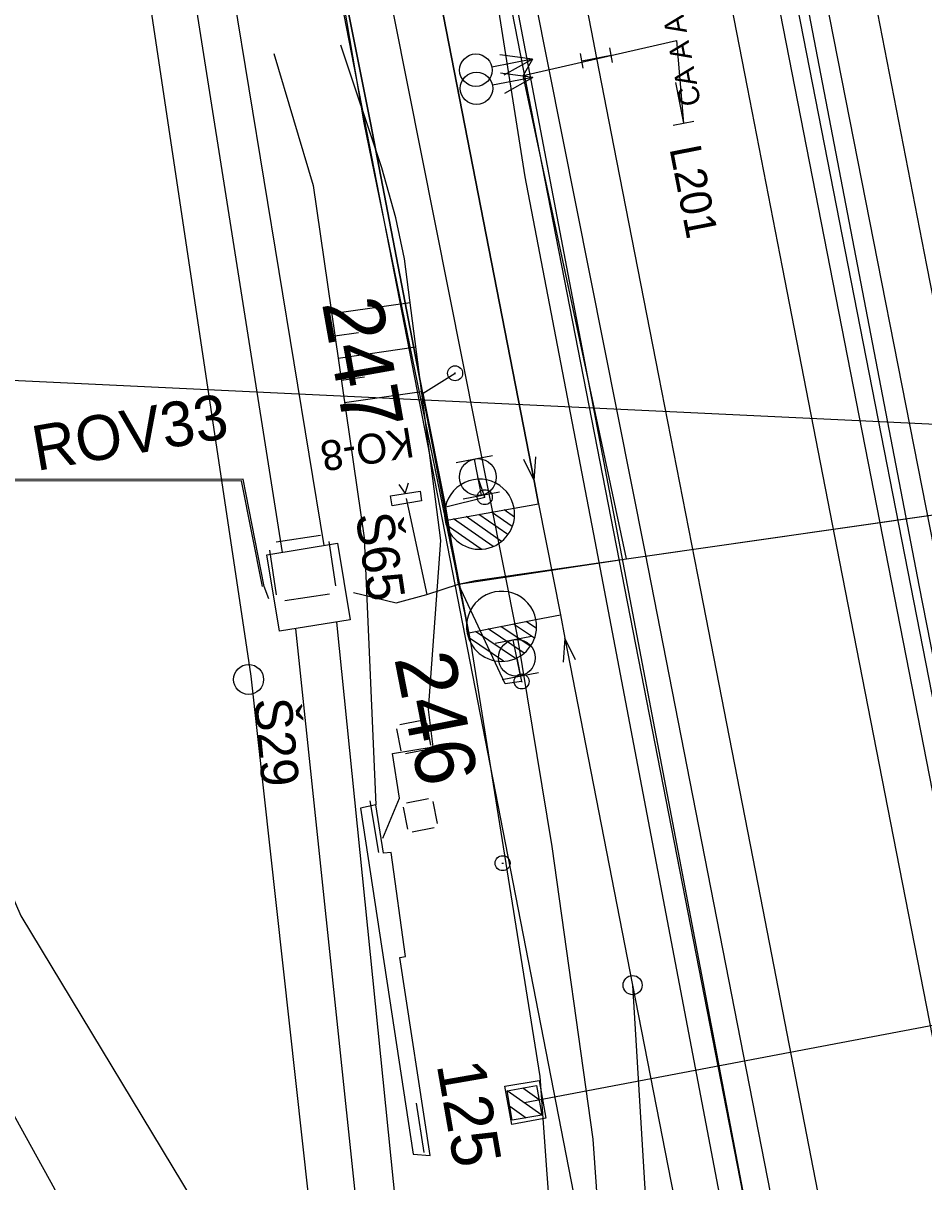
# Model space of a CAD drawing. Extents: x -545846 to -545044, y -1122650 to -1119108.
# Drawn here: x -545637.44 to -545607.35, y -1119747.46 to -1119708.74 of the extents above; entities that cross this region are included whole.
import ezdxf

# ---------------------------------------------------------------- set-up
doc = ezdxf.new("R2010")
doc.units = 0
for name, color, linetype in [('osvětlené plochy-hodnota-obrys', 7, 'Continuous'), ('Vrstva 1 - Koleje', 7, 'Continuous'), ('Vrstva 11 - Trakce', 7, 'Continuous'), ('Vrstva 12', 7, 'Continuous'), ('Vrstva 12 - Trakce zaklady', 7, 'Continuous'), ('Vrstva 17', 7, 'Continuous'), ('Vrstva 2 - Vyhybky', 7, 'Continuous'), ('Vrstva 25', 7, 'Continuous'), ('Vrstva 26', 7, 'Continuous'), ('Vrstva 27', 7, 'Continuous'), ('Vrstva 28 - zabzar', 7, 'Continuous'), ('Vrstva 3 - Lisy - Pocitaci body', 7, 'Continuous'), ('Vrstva 31', 7, 'Continuous'), ('Vrstva 34', 7, 'Continuous'), ('Vrstva 35', 7, 'Continuous'), ('Vrstva 36', 7, 'Continuous'), ('Vrstva 4 - Teren - stezky - prechody - plochy', 7, 'Continuous'), ('Vrstva 41', 7, 'Continuous'), ('Vrstva 43', 7, 'Continuous'), ('Vrstva 44', 7, 'Continuous'), ('Vrstva 48', 7, 'Continuous'), ('Vrstva 49', 7, 'Continuous'), ('Vrstva 50', 7, 'Continuous'), ('Vrstva 6 - Navesti', 7, 'Continuous'), ('Vrstva 62', 7, 'Continuous'), ('Vrstva 63', 7, 'Continuous')]:
    doc.layers.add(name, color=color, linetype=linetype)

msp = doc.modelspace()

# ---------------------------------------------------------------- linework, layer by layer
at = {"layer": 'osvětlené plochy-hodnota-obrys'}
for points in [[(-545716.386, -1119223.717), (-545705.994, -1119221.66), (-545669.439, -1119408.759), (-545659.4, -1119462.635), (-545647.69, -1119521.347), (-545640.519, -1119558.729), (-545633.585, -1119589.698), (-545629.517, -1119613.814), (-545623.042, -1119645.057), (-545619.034, -1119667.556), (-545607.519, -1119727.517)], [(-545610.895, -1119760.665), (-545622.836, -1119699.488), (-545637.26, -1119626.872), (-545653.542, -1119543.449), (-545716.386, -1119223.717)], [(-545618.794, -1119749.17), (-545664.282, -1119515.639)], [(-545607.519, -1119727.517), (-545482.536, -1120367.871), (-545465.73, -1120446.743)]]:
    msp.add_lwpolyline(points, dxfattribs=at)
at = {"layer": 'Vrstva 1 - Koleje'}
for points in [[(-545620.224, -1119724.797), (-545620.373, -1119724.031), (-545624.202, -1119704.383), (-545626.602, -1119682.532), (-545627.256, -1119676.573), (-545628.042, -1119669.394), (-545630.443, -1119647.544), (-545633.496, -1119631.903), (-545634.274, -1119627.915), (-545634.427, -1119627.13)], [(-545615.292, -1119700.416), (-545613.256, -1119710.876), (-545612.083, -1119716.896), (-545610.167, -1119726.739), (-545608.467, -1119735.46), (-545606.677, -1119744.638), (-545604.634, -1119755.121), (-545602.627, -1119765.413), (-545600.596, -1119775.823), (-545598.487, -1119786.628), (-545596.43, -1119797.186), (-545594.376, -1119807.724), (-545592.296, -1119818.383), (-545590.271, -1119828.778), (-545588.207, -1119839.366), (-545586.589, -1119847.665), (-545583.547, -1119863.26), (-545581.482, -1119873.852), (-545579.437, -1119884.331), (-545577.669, -1119893.4)], [(-545620.04, -1119700.93), (-545618.466, -1119708.981), (-545618.287, -1119709.904), (-545617.707, -1119712.885), (-545616.218, -1119720.514), (-545614.817, -1119727.693), (-545612.814, -1119737.973), (-545610.755, -1119748.533), (-545609.137, -1119756.825), (-545607.54, -1119765.023), (-545606.208, -1119771.849), (-545604.163, -1119782.329), (-545602.108, -1119792.879), (-545600.005, -1119803.67), (-545598.048, -1119813.712), (-545596.051, -1119823.937), (-545594.041, -1119834.228), (-545591.245, -1119848.57), (-545589.268, -1119858.708), (-545587.271, -1119868.949), (-545585.312, -1119878.984), (-545583.448, -1119888.544), (-545581.461, -1119898.732)], [(-545624.202, -1119704.383), (-545620.373, -1119724.031), (-545620.224, -1119724.797)], [(-545609.289, -1119706.39), (-545607.258, -1119716.828), (-545605.385, -1119726.4), (-545604.749, -1119729.676), (-545602.629, -1119740.555), (-545600.686, -1119750.508), (-545598.795, -1119760.226), (-545596.798, -1119770.466), (-545594.897, -1119780.215), (-545592.936, -1119790.271), (-545591.004, -1119800.184), (-545589.134, -1119809.787), (-545587.162, -1119819.904), (-545585.454, -1119828.656), (-545583.635, -1119837.965), (-545581.894, -1119846.888), (-545579.772, -1119857.774), (-545577.858, -1119867.605), (-545575.847, -1119877.904), (-545574.063, -1119887.086), (-545572.15, -1119896.857)], [(-545620.224, -1119724.797), (-545619.495, -1119728.51)], [(-545619.495, -1119728.51), (-545619.342, -1119729.295), (-545617.081, -1119740.889), (-545616.115, -1119756.897), (-545615.896, -1119760.311), (-545615.76, -1119762.434)], [(-545619.495, -1119728.51), (-545619.342, -1119729.295), (-545617.081, -1119740.889), (-545614.014, -1119756.616), (-545613.347, -1119760.026), (-545611.356, -1119770.277), (-545609.291, -1119780.868), (-545607.284, -1119791.169), (-545605.791, -1119798.836), (-545605.539, -1119800.128), (-545603.55, -1119810.316), (-545601.73, -1119819.637), (-545599.797, -1119829.553), (-545597.8, -1119839.791), (-545595.924, -1119849.399), (-545593.688, -1119860.879), (-545591.957, -1119869.777), (-545589.995, -1119879.817), (-545588.126, -1119889.394), (-545586.206, -1119899.252)]]:
    msp.add_lwpolyline(points, dxfattribs=at)
at = {"layer": 'Vrstva 11 - Trakce'}
for p, q in [((-545621.27, -1119744.417), (-545620.117, -1119745.229)), ((-545620.748, -1119744.327), (-545620.208, -1119744.707)), ((-545621.183, -1119744.937), (-545620.636, -1119745.322))]:
    msp.add_line(p, q, dxfattribs=at)
msp.add_lwpolyline([(-545556.873, -1119732.708), (-545581.366, -1119737.374), (-545620.695, -1119744.825)], dxfattribs=at)
msp.add_lwpolyline([(-545620.288, -1119744.247), (-545620.117, -1119745.232), (-545621.102, -1119745.403), (-545621.273, -1119744.418)], close=True, dxfattribs=at)
at = {"layer": 'Vrstva 12'}
msp.add_lwpolyline([(-545625.148, -1119736.458), (-545625.404, -1119736.479), (-545625.662, -1119734.867), (-545626.175, -1119734.971), (-545624.412, -1119746.538), (-545623.847, -1119746.584), (-545624.862, -1119739.966), (-545624.668, -1119739.936)], close=True, dxfattribs=at)
at = {"layer": 'Vrstva 12 - Trakce zaklady'}
msp.add_lwpolyline([(-545620.2, -1119744.079), (-545619.982, -1119745.334), (-545621.111, -1119745.55), (-545621.345, -1119744.265), (-545620.2, -1119744.079)], dxfattribs=at)
at = {"layer": 'Vrstva 17'}
for p, q in [((-545625.864, -1119734.724), (-545625.569, -1119736.452)), ((-545624.314, -1119744.838), (-545624.052, -1119746.488))]:
    msp.add_line(p, q, dxfattribs=at)
at = {"layer": 'Vrstva 2 - Vyhybky'}
for p, q in [((-545623.347, -1119725.355), (-545621.042, -1119724.945)), ((-545621.029, -1119725.244), (-545621.373, -1119725.004)), ((-545621.042, -1119724.945), (-545620.224, -1119724.797)), ((-545623.347, -1119725.356), (-545623.347, -1119725.355)), ((-545621.744, -1119726.228), (-545623.066, -1119725.305)), ((-545621.457, -1119726.057), (-545622.643, -1119725.23)), ((-545621.247, -1119725.833), (-545622.219, -1119725.154)), ((-545621.101, -1119725.564), (-545621.796, -1119725.08)), ((-545622.145, -1119726.318), (-545623.307, -1119725.508)), ((-545620.31, -1119728.672), (-545619.495, -1119728.51)), ((-545622.608, -1119729.123), (-545620.31, -1119728.672)), ((-545620.5, -1119729.564), (-545621.484, -1119728.902)), ((-545620.359, -1119729.293), (-545621.062, -1119728.82)), ((-545620.292, -1119728.971), (-545620.64, -1119728.737)), ((-545622.608, -1119729.124), (-545622.608, -1119729.123)), ((-545621.389, -1119730.065), (-545622.565, -1119729.275)), ((-545620.989, -1119729.968), (-545622.328, -1119729.068)), ((-545620.706, -1119729.791), (-545621.906, -1119728.985))]:
    msp.add_line(p, q, dxfattribs=at)
for points in [[(-545628.408, -1119682.795), (-545624.202, -1119704.383), (-545620.373, -1119724.031), (-545620.224, -1119724.797)], [(-545620.724, -1119723.312), (-545620.373, -1119724.031), (-545620.318, -1119723.233)], [(-545619.495, -1119728.51), (-545619.342, -1119729.295), (-545617.081, -1119740.889), (-545614.014, -1119756.616)], [(-545618.991, -1119730.014), (-545619.342, -1119729.295), (-545619.397, -1119730.093)], [(-545617.081, -1119740.889), (-545616.115, -1119756.897)]]:
    msp.add_lwpolyline(points, dxfattribs=at)
msp.add_circle((-545617.081, -1119740.889), 0.32, dxfattribs=at)
for centre, radius, start, end in [((-545622.193, -1119725.149), 1.17, 10.0337, 190.5033), ((-545622.194, -1119725.15), 1.171, 190.1233, 10.0841), ((-545621.458, -1119728.896), 1.17, 11.0374, 191.507), ((-545621.459, -1119728.898), 1.171, 191.127, 11.0878)]:
    msp.add_arc(centre, radius, start, end, dxfattribs=at)
at = {"layer": 'Vrstva 26'}
msp.add_lwpolyline([(-545629.45, -1119727.57), (-545630.15, -1119724.03), (-545639.1, -1119724.04), (-545639.35, -1119723.56), (-545638.56, -1119723.44), (-545638.81, -1119723.24), (-545638.97, -1119722.74), (-545638.995, -1119722.515), (-545638.995, -1119722.515)], dxfattribs=at)
at = {"layer": 'Vrstva 27'}
for p, q in [((-545625.17, -1119724.539), (-545625.167, -1119724.535)), ((-545622.015, -1119724.605), (-545622.025, -1119724.555)), ((-545620.794, -1119730.715), (-545620.786, -1119730.765))]:
    msp.add_line(p, q, dxfattribs=at)
msp.add_lwpolyline([(-545624.894, -1119724.153), (-545624.677, -1119724.455), (-545624.565, -1119724.1)], dxfattribs=at)
msp.add_lwpolyline([(-545625.17, -1119724.535), (-545624.183, -1119724.376), (-545624.13, -1119724.705), (-545625.117, -1119724.864)], close=True, dxfattribs=at)
for centre in [(-545622.02, -1119724.58), (-545620.79, -1119730.74)]:
    msp.add_circle(centre, 0.25, dxfattribs=at)
at = {"layer": 'Vrstva 28 - zabzar'}
msp.add_line((-545623.01, -1119720.465), (-545623.01, -1119720.415), dxfattribs=at)
for points in [[(-545626.41, -1119727.77), (-545624.98, -1119728.11), (-545623.96, -1119727.83), (-545622.9, -1119727.49), (-545622.33, -1119727.37), (-545617.28, -1119726.64), (-545619.25, -1119717.45), (-545620.74, -1119710.48), (-545615.61, -1119709.32), (-545615.38, -1119712.08)], [(-545620.43, -1119709.94), (-545620.74, -1119710.48), (-545620.41, -1119710.55)], [(-545620.95, -1119729.95), (-545620.79, -1119730.74), (-545621.34, -1119730.82), (-545622.9, -1119727.49), (-545623.32, -1119724.9), (-545624.08, -1119721.1), (-545623.01, -1119720.44)], [(-545623.32, -1119724.9), (-545622.02, -1119724.58), (-545622.25, -1119723.91)], [(-545624.65, -1119724.62), (-545624.51, -1119725.24), (-545623.96, -1119727.83)], [(-545617.28, -1119726.64), (-545602.93, -1119724.58)]]:
    msp.add_lwpolyline(points, dxfattribs=at)
msp.add_circle((-545623.01, -1119720.44), 0.25, dxfattribs=at)
at = {"layer": 'Vrstva 3 - Lisy - Pocitaci body'}
for p, q in [((-545620.43, -1119709.94), (-545621.784, -1119710.205)), ((-545620.43, -1119709.94), (-545621.512, -1119709.8)), ((-545620.43, -1119709.94), (-545621.379, -1119710.477)), ((-545618.73, -1119710.245), (-545618.826, -1119709.754)), ((-545618.778, -1119709.999), (-545617.796, -1119709.809)), ((-545617.748, -1119710.054), (-545617.844, -1119709.563)), ((-545620.41, -1119710.55), (-545621.765, -1119710.814)), ((-545620.41, -1119710.55), (-545621.492, -1119710.409)), ((-545620.41, -1119710.55), (-545621.36, -1119711.086)), ((-545622.973, -1119723.423), (-545621.763, -1119723.187)), ((-545622.132, -1119724.515), (-545622.368, -1119723.305)), ((-545622.737, -1119724.633), (-545621.527, -1119724.397)), ((-545621.673, -1119729.463), (-545620.463, -1119729.227)), ((-545620.832, -1119730.555), (-545621.068, -1119729.345)), ((-545621.437, -1119730.673), (-545620.227, -1119730.437))]:
    msp.add_line(p, q, dxfattribs=at)
for centre, radius in [((-545622.317, -1119710.307), 0.542), ((-545622.297, -1119710.915), 0.542), ((-545622.251, -1119723.908), 0.616), ((-545620.951, -1119729.948), 0.616)]:
    msp.add_circle(centre, radius, dxfattribs=at)
at = {"layer": 'Vrstva 31'}
for points in [[(-545629.45, -1119727.57), (-545630.15, -1119724.03), (-545639.1, -1119724.04), (-545638.56, -1119723.44)], [(-545629.238, -1119727.978), (-545629.39, -1119727.57), (-545630.09, -1119723.98), (-545638.456, -1119723.984), (-545638.56, -1119723.44)]]:
    msp.add_lwpolyline(points, dxfattribs=at)
at = {"layer": 'Vrstva 34'}
for p, q in [((-545628.993, -1119726.071), (-545627.51, -1119725.849)), ((-545627.225, -1119726.059), (-545627.003, -1119727.542)), ((-545628.981, -1119727.839), (-545629.203, -1119726.356)), ((-545627.213, -1119727.827), (-545628.696, -1119728.049))]:
    msp.add_line(p, q, dxfattribs=at)
at = {"layer": 'Vrstva 35'}
for p, q in [((-545628.775, -1119726.428), (-545634.574, -1119689.677)), ((-545627.388, -1119726.198), (-545633.404, -1119689.501)), ((-545620.74, -1119710.48), (-545615.61, -1119709.32)), ((-545617.28, -1119726.64), (-545602.93, -1119724.58)), ((-545622.9, -1119727.49), (-545617.28, -1119726.64)), ((-545622.536, -1119772.489), (-545626.966, -1119728.759)), ((-545623.729, -1119772.61), (-545628.334, -1119728.982))]:
    msp.add_line(p, q, dxfattribs=at)
at = {"layer": 'Vrstva 36'}
for points in [[(-545629.3, -1119726.511), (-545626.94, -1119726.115), (-545626.518, -1119728.679), (-545628.873, -1119729.062), (-545629.3, -1119726.511)], [(-545629.3, -1119726.511), (-545626.94, -1119726.115)], [(-545626.94, -1119726.115), (-545626.94, -1119726.115), (-545626.518, -1119728.679), (-545626.518, -1119728.679)], [(-545628.873, -1119729.062), (-545629.3, -1119726.511), (-545629.3, -1119726.511)], [(-545626.518, -1119728.679), (-545628.873, -1119729.062), (-545628.873, -1119729.062)]]:
    msp.add_lwpolyline(points, dxfattribs=at)
at = {"layer": 'Vrstva 4 - Teren - stezky - prechody - plochy'}
for points in [[(-545668.116, -1119499.514), (-545665.721, -1119507.929), (-545662.615, -1119519.622), (-545659.148, -1119534.332), (-545655.765, -1119550.675), (-545641.939, -1119621.169), (-545637.993, -1119641.248), (-545631.568, -1119675.037), (-545626.43, -1119701.616), (-545620.933, -1119729.23), (-545619.776, -1119736.256), (-545618.414, -1119746.042), (-545618.118, -1119750.155), (-545617.307, -1119763.323), (-545616.619, -1119772.592), (-545616.223, -1119779.957), (-545616.135, -1119786.617)], [(-545628.853, -1119622.763), (-545624.686, -1119644.063), (-545616.354, -1119686.873), (-545605.869, -1119740.58), (-545597.619, -1119782.547), (-545588.666, -1119828.365), (-545577.778, -1119884.555), (-545567.555, -1119936.921), (-545555.278, -1120000.024), (-545543.118, -1120062.357), (-545532.633, -1120116.151), (-545522.436, -1120168.075), (-545510.345, -1120230.332), (-545500.633, -1120280.001), (-545495.304, -1120307.199), (-545490.342, -1120331.504), (-545485.9, -1120353.688), (-545480.839, -1120378)], [(-545627.289, -1119622.488), (-545623.041, -1119643.798), (-545614.848, -1119686.378), (-545604.257, -1119740.381), (-545596.077, -1119782.585), (-545587.168, -1119828.353), (-545576.202, -1119884.317), (-545565.971, -1119936.976), (-545553.74, -1119999.834), (-545541.535, -1120062.236), (-545531.079, -1120116.013), (-545520.819, -1120168.515), (-545508.831, -1120230.344), (-545499.12, -1120279.845), (-545497.248, -1120289.164), (-545495.162, -1120299.078), (-545493.408, -1120306.853), (-545489.261, -1120323.659), (-545486.768, -1120332.638), (-545482.019, -1120349.033), (-545479.258, -1120359.037), (-545477.044, -1120368.814), (-545475.362, -1120376.928)], [(-545637.393, -1119653.539), (-545633.274, -1119675.3), (-545627.579, -1119703.177), (-545627.31, -1119704.719), (-545626.06, -1119712.07), (-545622.496, -1119729.428)], [(-545488.754, -1120379.549), (-545491.925, -1120363.788), (-545496.278, -1120342.782), (-545500.506, -1120321.731), (-545508.599, -1120280.828), (-545518.82, -1120228.621), (-545531.029, -1120165.923), (-545540.626, -1120116.248), (-545552.245, -1120057.042), (-545557.488, -1120030.03), (-545563.439, -1119999.512), (-545572.128, -1119954.79), (-545581.61, -1119906.246), (-545591.458, -1119855.639), (-545600.962, -1119806.943), (-545610.434, -1119758.233), (-545616.648, -1119726.461), (-545621.696, -1119701.088), (-545622.533, -1119696.196), (-545623.462, -1119696.331)], [(-545490.916, -1120379.972), (-545493.99, -1120364.147), (-545502.163, -1120322.09), (-545510.164, -1120281.035), (-545520.235, -1120229.023), (-545532.517, -1120166.017), (-545542.296, -1120116.028), (-545553.809, -1120057.082), (-545558.932, -1120030.597), (-545564.969, -1119999.794), (-545573.753, -1119955.036), (-545583.127, -1119906.578), (-545593.017, -1119855.856), (-545602.553, -1119806.891), (-545612.123, -1119758.671), (-545618.333, -1119726.047), (-545620.676, -1119713.873), (-545622.612, -1119701.558), (-545623.462, -1119696.331)], [(-545622.496, -1119729.428), (-545625.835, -1119712.063), (-545627.31, -1119704.719)], [(-545627.31, -1119704.719), (-545625.835, -1119712.063), (-545622.496, -1119729.428), (-545620.183, -1119743.94), (-545619.945, -1119747.203), (-545618.749, -1119763.231), (-545617.479, -1119774.393), (-545617.097, -1119780.69), (-545617.068, -1119786.701), (-545616.135, -1119786.617)]]:
    msp.add_lwpolyline(points, dxfattribs=at)
at = {"layer": 'Vrstva 41'}
for p, q in [((-545624.81, -1119733.059), (-545624.953, -1119732.322)), ((-545624.855, -1119732.176), (-545624.118, -1119732.033)), ((-545623.972, -1119732.131), (-545623.829, -1119732.868)), ((-545623.927, -1119733.014), (-545624.664, -1119733.157)), ((-545624.636, -1119734.795), (-545623.9, -1119734.651)), ((-545624.591, -1119735.678), (-545624.735, -1119734.942)), ((-545623.753, -1119734.75), (-545623.609, -1119735.486)), ((-545623.708, -1119735.633), (-545624.444, -1119735.777))]:
    msp.add_line(p, q, dxfattribs=at)
at = {"layer": 'Vrstva 43'}
msp.add_circle((-545629.91, -1119730.672), 0.5, dxfattribs=at)
at = {"layer": 'Vrstva 44'}
for points in [[(-545654.9, -1119582.222), (-545645.965, -1119631.818), (-545637.145, -1119681.816), (-545629.836, -1119730.566), (-545626.416, -1119761.521), (-545622.849, -1119813.009), (-545619.592, -1119863.304), (-545618.858, -1119914.175), (-545618.881, -1119950.565), (-545618.715, -1119963.415), (-545629.02, -1119997.179)], [(-545622.746, -1119648.835), (-545613.361, -1119699.038), (-545602.122, -1119756.581), (-545611.004, -1119758.624), (-545611.36, -1119758.757)], [(-545632.322, -1119650.948), (-545622.321, -1119700.988), (-545611.338, -1119758.596), (-545611.36, -1119758.757), (-545611.449, -1119758.784)]]:
    msp.add_lwpolyline(points, dxfattribs=at)
at = {"layer": 'Vrstva 48'}
for p, q in [((-545627.132, -1119718.446), (-545624.516, -1119718.068)), ((-545627.025, -1119719.188), (-545626.243, -1119719.075)), ((-545626.918, -1119719.93), (-545624.323, -1119719.556)), ((-545626.811, -1119720.672), (-545626.036, -1119720.561)), ((-545626.704, -1119721.415), (-545624.131, -1119721.044))]:
    msp.add_line(p, q, dxfattribs=at)
at = {"layer": 'Vrstva 49'}
msp.add_line((-545625.464, -1119713.575), (-545626.833, -1119709.475), dxfattribs=at)
for points in [[(-545629.072, -1119709.755), (-545627.75, -1119714.159), (-545626.051, -1119725.941), (-545625.662, -1119734.867)], [(-545625.431, -1119735.975), (-545624.865, -1119734.64), (-545625.106, -1119733.146), (-545623.741, -1119732.926), (-545623.897, -1119731.682), (-545623.486, -1119726.025), (-545624.705, -1119716.608), (-545624.986, -1119715.238), (-545625.464, -1119713.575)]]:
    msp.add_lwpolyline(points, dxfattribs=at)
at = {"layer": 'Vrstva 50'}
msp.add_line((-545621.45, -1119736.813), (-545621.4, -1119736.813), dxfattribs=at)
msp.add_circle((-545621.425, -1119736.813), 0.25, dxfattribs=at)
at = {"layer": 'Vrstva 6 - Navesti'}
for p, q in [((-545615.646, -1119710.72), (-545615.38, -1119712.08)), ((-545615.723, -1119712.147), (-545615.037, -1119712.013))]:
    msp.add_line(p, q, dxfattribs=at)
at = {"layer": 'Vrstva 62'}
for points in [[(-545640.514, -1119731.132), (-545640.565, -1119731.562), (-545637.52, -1119738.574), (-545631.121, -1119749.176), (-545627.046, -1119780.523), (-545625.616, -1119808.19), (-545622.475, -1119817.927), (-545620.564, -1119842.07), (-545627.793, -1119850.696), (-545627.914, -1119866.869), (-545625.298, -1119872.204), (-545622.371, -1119881.231), (-545621.372, -1119899.088), (-545619.713, -1119906.036), (-545619.415, -1119919.615), (-545622.171, -1119926.525), (-545621.036, -1119950.949)], [(-545638.201, -1119873.676), (-545634.87, -1119872.217), (-545634.795, -1119868.379), (-545631.845, -1119861.885), (-545633.332, -1119850.19), (-545628.466, -1119836.59), (-545630.287, -1119812.477), (-545629.754, -1119789.831), (-545632.421, -1119759.531), (-545636.379, -1119747.707), (-545644.025, -1119733.886)]]:
    msp.add_lwpolyline(points, dxfattribs=at)
at = {"layer": 'Vrstva 63'}
msp.add_line((-545558.013, -1119724.486), (-545666.337, -1119719.323), dxfattribs=at)

# ---------------------------------------------------------------- texts
at = {"layer": 'Vrstva 11 - Trakce'}
msp.add_text('125', height=1.6, rotation=279.8542, dxfattribs=at).set_placement((-545623.63, -1119743.545))
at = {"layer": 'Vrstva 2 - Vyhybky'}
for s, rotation, p in [('247', 280.1037, (-545627.464, -1119718.088)), ('246', 281.0392, (-545625.047, -1119729.961))]:
    msp.add_text(s, height=2, rotation=rotation, dxfattribs=at).set_placement(p)
at = {"layer": 'Vrstva 25'}
msp.add_text('ROV33', height=1.5, rotation=9.8439, dxfattribs=at).set_placement((-545636.992, -1119723.706))
at = {"layer": 'Vrstva 27'}
msp.add_text('KO-8', height=1, rotation=189.1798, dxfattribs=at).set_placement((-545624.487, -1119722.239))
at = {"layer": 'Vrstva 34'}
msp.add_text('Š65', height=1.25, rotation=278.5336, dxfattribs=at).set_placement((-545626.342, -1119725.178))
at = {"layer": 'Vrstva 43'}
msp.add_text('Š29', height=1.25, rotation=275.321, dxfattribs=at).set_placement((-545629.734, -1119731.342))
at = {"layer": 'Vrstva 6 - Navesti'}
for s, height, rotation, p in [('  CA A A A A A ', 0.7, 101.0739, (-545614.693, -1119711.946)), ('L201', 1.05, 281.0629, (-545615.854, -1119712.925))]:
    msp.add_text(s, height=height, rotation=rotation, dxfattribs=at).set_placement(p)

doc.saveas('drawing.dxf')
